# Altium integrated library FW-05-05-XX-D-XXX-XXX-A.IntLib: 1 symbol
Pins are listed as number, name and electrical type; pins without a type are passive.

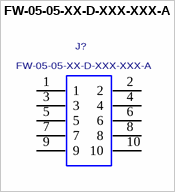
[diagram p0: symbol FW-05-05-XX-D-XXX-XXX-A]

## FW-05-05-XX-D-XXX-XXX-A
designator J?
.050 x .050 SURFACE MOUNT BOARD SPACERS, 10 PINS.; MANUFACTURER: SAMTEC
footprint FW-05-05-XX-D-XXX-XXX-A
pins: 1, 2, 3, 4, 5, 6, 7, 8, 9, 10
